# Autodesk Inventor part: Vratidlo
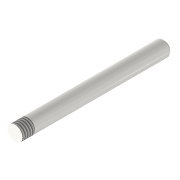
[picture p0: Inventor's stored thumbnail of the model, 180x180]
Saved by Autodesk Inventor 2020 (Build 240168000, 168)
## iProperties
Created: 2025-03
Part Number: Vratidlo
Material: Ocel
Document SubType Name: Modeling
Designer: doma
Density: 7.85 g/cm^3
Appearance: Ocel
Mass: 13.3172 g
Surface Area: 11.8752 cm^2
Volume: 1.69646 cm^3
Author: doma
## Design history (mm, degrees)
sketch "Náčrt1"
  geometry: C1 r 3 at (0, 0); 1 further point
  constraints: 1 centre point, 1 coincident
  dimensions: "d0" = 6 diameter of C1
extrude "Vysunutí1" new body sketch "Náčrt1" distance "d1" = 60; taper "d2" = 0 deg
feature "Závit1" dims "d3" = 5, "d4" = 0
chamfer "Zkosení1" distance "d5" = 1; stored, may be unused: second distance "d6" = 2, angle "d7" = 45 deg
node "Těleso1"
